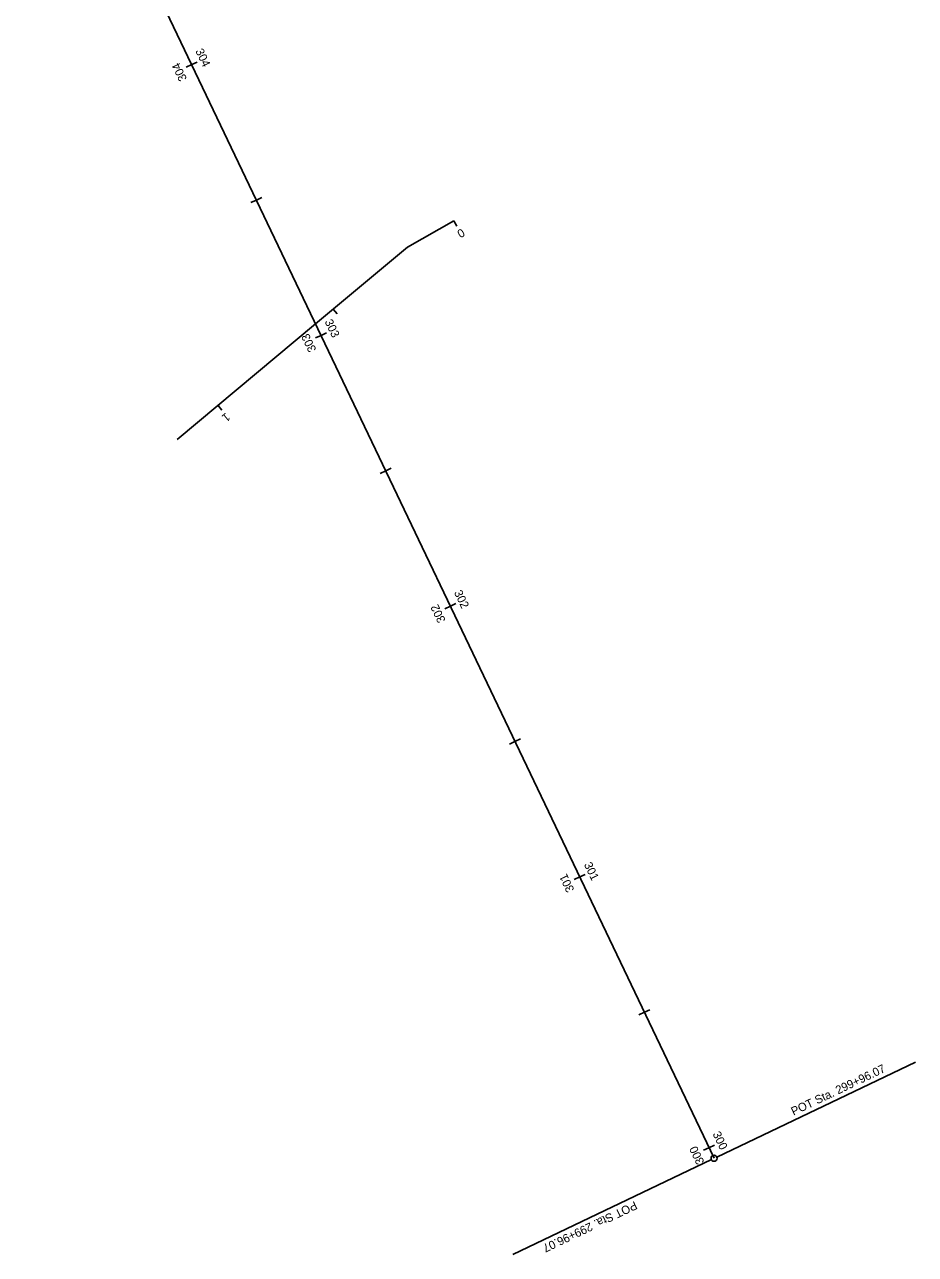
# Model space of a CAD drawing. Extents: x 2082566 to 2083025, y 593028 to 593822.
# Drawn here: x 2082728.5 to 2083025.3, y 593028.2 to 593438.1 of the extents above; entities that cross this region are included whole.
import ezdxf

# ---------------------------------------------------------------- set-up
doc = ezdxf.new("R2010")
doc.units = 0
for name, color, linetype in [('CL_P_Construction', 7, 'Continuous'), ('CL_X_RW', 7, 'Continuous'), ('RW_X_CL_20', 7, 'Continuous')]:
    doc.layers.add(name, color=color, linetype=linetype)

msp = doc.modelspace()

# ---------------------------------------------------------------- linework, layer by layer
at = {"layer": 'CL_P_Construction'}
for p, q in [((2082871.44, 593372.69), (2082856.08, 593363.93)), ((2082871.44, 593372.69), (2082872.43, 593370.95)), ((2082856.08, 593363.93), (2082825.43, 593338.3)), ((2082831.28, 593343.2), (2082832.57, 593341.66)), ((2082825.43, 593338.3), (2082779.36, 593299.78)), ((2082792.93, 593311.12), (2082794.21, 593309.59))]:
    msp.add_line(p, q, dxfattribs=at)
at = {"layer": 'CL_X_RW'}
for p, q in [((2082958.18, 593060.22), (2082728.49, 593541.35)), ((2082958.18, 593060.22), (2082728.49, 593541.35)), ((2082784.16, 593424.74), (2082782.35, 593423.88)), ((2082805.7, 593379.61), (2082803.89, 593378.75)), ((2082827.24, 593334.49), (2082825.44, 593333.63)), ((2082848.78, 593289.37), (2082846.98, 593288.51)), ((2082870.32, 593244.25), (2082868.52, 593243.39)), ((2082891.86, 593199.13), (2082890.06, 593198.27)), ((2082913.41, 593154.01), (2082911.6, 593153.14)), ((2082934.95, 593108.88), (2082933.14, 593108.02)), ((2082956.49, 593063.76), (2082954.68, 593062.9)), ((2082957.28, 593059.79), (2082891.11, 593028.2))]:
    msp.add_line(p, q, dxfattribs=at)
msp.add_circle((2082958.18, 593060.22), 1, dxfattribs=at)
at = {"layer": 'RW_X_CL_20'}
for p, q in [((2082958.18, 593060.22), (2082728.49, 593541.35)), ((2082784.16, 593424.74), (2082785.96, 593425.6)), ((2082805.7, 593379.61), (2082807.5, 593380.48)), ((2082827.24, 593334.49), (2082829.05, 593335.35)), ((2082848.78, 593289.37), (2082850.59, 593290.23)), ((2082870.32, 593244.25), (2082872.13, 593245.11)), ((2082891.86, 593199.13), (2082893.67, 593199.99)), ((2082913.41, 593154.01), (2082915.21, 593154.87)), ((2082934.95, 593108.88), (2082936.75, 593109.75)), ((2082959.08, 593060.65), (2083025.25, 593092.24)), ((2082956.49, 593063.76), (2082958.29, 593064.62))]:
    msp.add_line(p, q, dxfattribs=at)
msp.add_circle((2082958.18, 593060.22), 1, dxfattribs=at)

# ---------------------------------------------------------------- texts
at = {"layer": 'CL_P_Construction'}
for s, rotation, p in [('0', 209.7015, (2082874.09, 593370.28)), ('1', 219.8982, (2082795.55, 593308.89))]:
    msp.add_text(s, height=2.8, rotation=rotation, dxfattribs=at).set_placement(p)
at = {"layer": 'CL_X_RW'}
for s, rotation, p in [('304', 115.52, (2082782.65, 593420.01)), ('303', 115.52, (2082825.75, 593329.73)), ('302', 115.52, (2082868.82, 593239.51)), ('301', 115.52, (2082911.7, 593149.69)), ('300', 115.52, (2082955.01, 593058.97)), ('POT Sta. 299+96.07', 205.52, (2082931.71, 593046.03))]:
    msp.add_text(s, height=2.8, rotation=rotation, dxfattribs=at).set_placement(p)
at = {"layer": 'RW_X_CL_20'}
for s, rotation, p in [('304', 295.52, (2082785.31, 593429.29)), ('303', 295.52, (2082828.37, 593339.09)), ('302', 295.52, (2082871.47, 593248.81)), ('301', 295.52, (2082914.75, 593158.15)), ('POT Sta. 299+96.07', 25.52, (2082984.65, 593074.4)), ('300', 295.52, (2082957.61, 593068.39))]:
    msp.add_text(s, height=2.8, rotation=rotation, dxfattribs=at).set_placement(p)

doc.saveas('drawing.dxf')
